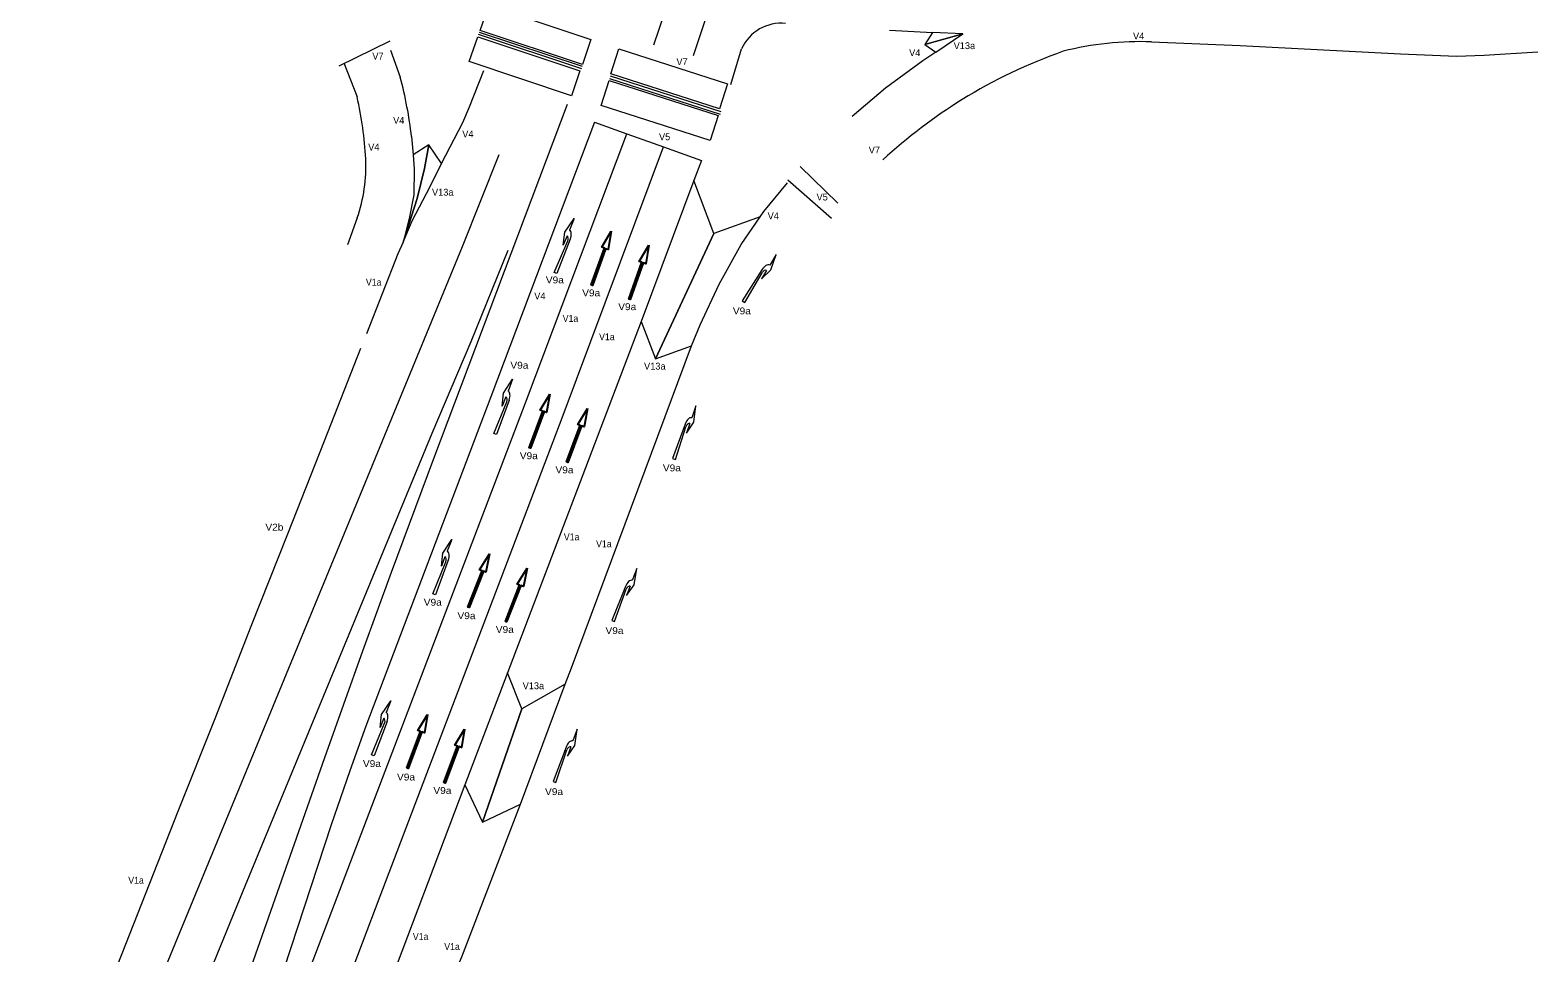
# Model space of a CAD drawing. Extents: x -598770 to -598612, y -1162818 to -1162391.
# Drawn here: x -598743 to -598611.6, y -1162737.1 to -1162656.8 of the extents above; entities that cross this region are included whole.
import ezdxf

# ---------------------------------------------------------------- set-up
doc = ezdxf.new("R2010")
doc.units = 0
doc.header["$LTSCALE"] = 0.24
doc.layers.add('1', color=7, linetype='Continuous', lineweight=25)
doc.layers.add('47', color=7, linetype='Continuous', lineweight=13)

msp = doc.modelspace()

# ---------------------------------------------------------------- linework, layer by layer
at = {"layer": '1'}
for points in [[(-598692.356, -1162674.292), (-598692.613, -1162675.9), (-598692.839, -1162675.819), (-598693.984, -1162679.02), (-598694.096, -1162678.98), (-598692.952, -1162675.778), (-598693.178, -1162675.698)], [(-598689.086, -1162675.522), (-598689.343, -1162677.13), (-598689.569, -1162677.049), (-598690.714, -1162680.25), (-598690.826, -1162680.21), (-598689.682, -1162677.008), (-598689.908, -1162676.928)], [(-598697.702, -1162688.485), (-598697.98, -1162690.089), (-598698.205, -1162690.005), (-598699.394, -1162693.191), (-598699.506, -1162693.149), (-598698.318, -1162689.964), (-598698.543, -1162689.88)], [(-598694.432, -1162689.725), (-598694.71, -1162691.329), (-598694.935, -1162691.245), (-598696.124, -1162694.431), (-598696.236, -1162694.389), (-598695.048, -1162691.204), (-598695.273, -1162691.12)], [(-598702.961, -1162702.397), (-598703.267, -1162703.996), (-598703.49, -1162703.908), (-598704.734, -1162707.072), (-598704.846, -1162707.028), (-598703.602, -1162703.864), (-598703.825, -1162703.776)], [(-598699.691, -1162703.647), (-598699.997, -1162705.246), (-598700.22, -1162705.158), (-598701.464, -1162708.322), (-598701.576, -1162708.278), (-598700.332, -1162705.114), (-598700.555, -1162705.026)], [(-598708.358, -1162716.373), (-598708.634, -1162717.978), (-598708.859, -1162717.894), (-598710.044, -1162721.081), (-598710.156, -1162721.039), (-598708.971, -1162717.852), (-598709.196, -1162717.769)], [(-598705.127, -1162717.661), (-598705.41, -1162719.264), (-598705.635, -1162719.18), (-598706.834, -1162722.361), (-598706.946, -1162722.319), (-598705.747, -1162719.137), (-598705.972, -1162719.053)]]:
    msp.add_lwpolyline(points, close=True, dxfattribs=at)
at = {"layer": '47'}
for p, q in [((-598668.09, -1162656.8), (-598664.36, -1162657)), ((-598716.061, -1162659.896), (-598711.608, -1162657.714)), ((-598694.919, -1162660.156), (-598703.928, -1162657.18)), ((-598694.841, -1162659.944), (-598703.821, -1162656.98)), ((-598711.6, -1162658.54), (-598710.74, -1162660.89)), ((-598681.94, -1162661.53), (-598680.99, -1162658.42)), ((-598715.66, -1162659.63), (-598714.5, -1162662.6)), ((-598692.437, -1162660.774), (-598682.807, -1162663.859)), ((-598692.511, -1162661), (-598682.858, -1162664.093)), ((-598709.75, -1162666.06), (-598709.62, -1162667.66)), ((-598699.81, -1162689.25), (-598691, -1162665.83)), ((-598696.64, -1162690.56), (-598687.79, -1162666.96)), ((-598684.48, -1162668.14), (-598685.14, -1162669.89)), ((-598675.873, -1162668.667), (-598672.616, -1162671.867)), ((-598676.96, -1162669.82), (-598673.16, -1162673.16)), ((-598714.48, -1162673.14), (-598715.32, -1162675.47)), ((-598695.58, -1162673.19), (-598695.997, -1162674.208)), ((-598677.974, -1162676.318), (-598678.544, -1162677.259)), ((-598700.952, -1162687.193), (-598701.345, -1162688.221)), ((-598684.98, -1162689.505), (-598685.335, -1162690.546)), ((-598706.246, -1162701.138), (-598706.643, -1162702.164)), ((-598690.124, -1162703.683), (-598690.514, -1162704.711)), ((-598711.571, -1162715.183), (-598711.978, -1162716.205)), ((-598695.327, -1162717.656), (-598695.699, -1162718.691))]:
    msp.add_line(p, q, dxfattribs=at)
for points in [[(-598685.18, -1162659.01), (-598682.44, -1162650.81), (-598678.78, -1162639.81), (-598676.01, -1162631.49), (-598669.81, -1162609.43), (-598665.71, -1162592.63), (-598660.52, -1162567.28), (-598657.82, -1162550.24), (-598655.55, -1162533.08), (-598653.64, -1162512.9), (-598653.24, -1162507.21), (-598652.17, -1162486.96), (-598650.81, -1162443.8), (-598650.17, -1162405.3)], [(-598688.64, -1162658.06), (-598686.79, -1162652.59), (-598679.89, -1162631.9)], [(-598645.26, -1162657.81), (-598637.54, -1162658.14), (-598623.58, -1162658.85), (-598618.7, -1162659.04), (-598616.28, -1162658.97), (-598611.6, -1162658.68)], [(-598664.07, -1162658.72), (-598665.2, -1162659.47), (-598668.46, -1162661.85), (-598671.36, -1162664.3)], [(-598707.13, -1162668.41), (-598705.27, -1162664.84), (-598704.69, -1162663.46), (-598703.44, -1162660.31)], [(-598696.2, -1162663.26), (-598707.83, -1162694.12), (-598711.54, -1162704.01), (-598714.04, -1162710.86), (-598717.34, -1162720.17), (-598728.64, -1162752.3), (-598735.08, -1162769.26)], [(-598693.82, -1162664.79), (-598702.84, -1162688.72), (-598713.75, -1162717.39), (-598715.12, -1162721.28), (-598716.75, -1162725.99), (-598732.65, -1162774.4)], [(-598693.82, -1162664.79), (-598691, -1162665.83), (-598687.79, -1162666.96), (-598684.48, -1162668.14)], [(-598702.14, -1162667.64), (-598705.35, -1162675.66), (-598715.83, -1162701.11), (-598732.7, -1162742.03), (-598734.74, -1162747.28), (-598741.96, -1162766.21), (-598742.99, -1162769.03)], [(-598679.38, -1162673.06), (-598679.05, -1162672.57), (-598677, -1162670.08)], [(-598696.202, -1162674.708), (-598696.529, -1162675.503), (-598696.389, -1162674.372), (-598695.58, -1162673.19)], [(-598710.49, -1162675.25), (-598710.94, -1162676.27), (-598713.68, -1162683.24)], [(-598695.919, -1162674.997), (-598697.084, -1162677.977), (-598697.316, -1162677.883), (-598696.131, -1162675.126)], [(-598701.36, -1162675.97), (-598704.6, -1162683.92), (-598707.98, -1162691.91), (-598724.47, -1162731.76), (-598730.99, -1162747.75)], [(-598678.823, -1162677.721), (-598679.269, -1162678.457), (-598678.442, -1162677.671), (-598677.974, -1162676.318)], [(-598679.224, -1162677.665), (-598680.927, -1162680.375), (-598680.713, -1162680.505), (-598679.202, -1162677.912)], [(-598689.73, -1162682.17), (-598701.39, -1162712.77), (-598705.1, -1162722.51)], [(-598714.19, -1162684.51), (-598717.37, -1162692.57), (-598720.57, -1162700.67), (-598723.76, -1162708.71), (-598726.91, -1162716.76), (-598730.11, -1162724.83), (-598736.46, -1162740.9)], [(-598696.36, -1162713.74), (-598695.82, -1162712.33), (-598685.36, -1162684.28)], [(-598701.538, -1162688.725), (-598701.846, -1162689.528), (-598701.733, -1162688.394), (-598700.952, -1162687.193)], [(-598726.06, -1162758.02), (-598723.44, -1162751.19), (-598699.81, -1162689.25)], [(-598701.248, -1162689.007), (-598702.343, -1162692.015), (-598702.577, -1162691.925), (-598701.457, -1162689.142)], [(-598685.51, -1162691.057), (-598685.788, -1162691.871), (-598685.149, -1162690.927), (-598684.98, -1162689.505)], [(-598722.67, -1162759.28), (-598718.64, -1162748.46), (-598712.49, -1162732.21), (-598696.64, -1162690.56)], [(-598685.914, -1162691.089), (-598686.998, -1162694.1), (-598686.762, -1162694.18), (-598685.839, -1162691.325)], [(-598706.838, -1162702.668), (-598707.148, -1162703.47), (-598707.031, -1162702.336), (-598706.246, -1162701.138)], [(-598706.549, -1162702.951), (-598707.653, -1162705.955), (-598707.887, -1162705.865), (-598706.758, -1162703.085)], [(-598690.706, -1162705.216), (-598691.012, -1162706.02), (-598690.34, -1162705.098), (-598690.124, -1162703.683)], [(-598691.111, -1162705.233), (-598692.297, -1162708.206), (-598692.063, -1162708.294), (-598691.044, -1162705.472)], [(-598712.177, -1162716.707), (-598712.495, -1162717.506), (-598712.367, -1162716.373), (-598711.571, -1162715.183)], [(-598711.891, -1162716.993), (-598713.024, -1162719.986), (-598713.256, -1162719.894), (-598712.101, -1162717.125)], [(-598695.882, -1162719.199), (-598696.172, -1162720.009), (-598695.518, -1162719.075), (-598695.327, -1162717.656)], [(-598696.286, -1162719.224), (-598697.418, -1162722.218), (-598697.182, -1162722.302), (-598696.215, -1162719.462)], [(-598705.1, -1162722.51), (-598712.39, -1162741.77), (-598713.95, -1162745.97), (-598721.88, -1162767.78)], [(-598720.58, -1162768.16), (-598715.47, -1162758.87), (-598711.57, -1162751.14), (-598707.93, -1162743.46), (-598705.37, -1162737.49), (-598700.25, -1162724.18)]]:
    msp.add_lwpolyline(points, dxfattribs=at)
for points in [[(-598703.027, -1162654.647), (-598694.128, -1162657.617), (-598694.848, -1162659.777), (-598703.766, -1162656.807)], [(-598703.982, -1162657.365), (-598695.083, -1162660.335), (-598695.803, -1162662.495), (-598704.721, -1162659.525)], [(-598664.36, -1162657), (-598665.03, -1162658.05), (-598661.72, -1162657.12)], [(-598665.03, -1162658.05), (-598664.07, -1162658.72), (-598661.72, -1162657.12)], [(-598691.7, -1162658.424), (-598682.207, -1162661.466), (-598682.903, -1162663.64), (-598692.397, -1162660.598)], [(-598692.534, -1162661.185), (-598683.041, -1162664.227), (-598683.737, -1162666.401), (-598693.231, -1162663.359)], [(-598708.25, -1162666.77), (-598708.62, -1162668.85), (-598709.26, -1162671.44), (-598710.49, -1162675.25), (-598709.69, -1162673.39), (-598708.13, -1162670.41), (-598707.13, -1162668.41)], [(-598708.25, -1162666.77), (-598709.62, -1162667.66), (-598709.52, -1162668.89), (-598709.56, -1162671.14), (-598709.95, -1162673.19), (-598710.49, -1162675.25), (-598709.26, -1162671.44), (-598708.62, -1162668.85)], [(-598685.14, -1162669.89), (-598689.73, -1162682.17), (-598688.48, -1162685.4), (-598683.41, -1162674.51)], [(-598683.41, -1162674.51), (-598688.48, -1162685.4), (-598685.36, -1162684.28), (-598684.61, -1162682.46), (-598682.95, -1162678.92), (-598681.02, -1162675.46), (-598679.38, -1162673.06)], [(-598701.39, -1162712.77), (-598705.1, -1162722.51), (-598703.56, -1162725.76), (-598700.14, -1162715.88)], [(-598696.36, -1162713.74), (-598700.14, -1162715.88), (-598703.56, -1162725.76), (-598700.25, -1162724.18)]]:
    msp.add_lwpolyline(points, close=True, dxfattribs=at)
for centre, radius, start, end in [((-598677.536, -1162659.9634), 3.7832, 84.1441, 155.92246), ((-598646.2614, -1162685.0507), 27.2591, 87.89467, 104.24712), ((-598637.7345, -1162701.8354), 45.813, 109.42414, 121.65897), ((-598745.2256, -1162670.1734), 35.7132, 6.61393, 15.06668), ((-598744.1809, -1162669.4744), 30.4666, 2.77392, 13.04041), ((-598636.2065, -1162703.678), 48.1845, 122.05557, 132.37198), ((-598727.5693, -1162668.6592), 13.835, 341.10251, 2.73093)]:
    msp.add_arc(centre, radius, start, end, dxfattribs=at)
for centre, major_axis, ratio, start_param, end_param in [((-598696.3391, -1162675.0408), (0.1366, 0.3331), 0.625, 4.71238898, 6.28318531), ((-598696.2631, -1162674.8558), (0.2657, 0.6476), 0.531429, 4.71238898, 6.28318531), ((-598678.906, -1162677.8578), (-0.3625, -0.5988), 0.531429, 3.14159265, 4.71238898), ((-598679.0096, -1162678.0289), (-0.1864, -0.308), 0.625, 3.14159265, 4.71238898), ((-598701.5959, -1162688.8745), (0.2504, 0.6537), 0.531429, 4.71238898, 6.28318531), ((-598701.6674, -1162689.0613), (0.1288, 0.3362), 0.625, 4.71238898, 6.28318531), ((-598685.5616, -1162691.2087), (-0.2263, -0.6624), 0.531429, 3.14159265, 4.71238898), ((-598685.6262, -1162691.3979), (-0.1164, -0.3407), 0.625, 3.14159265, 4.71238898), ((-598706.9681, -1162703.0039), (0.1298, 0.3358), 0.625, 4.71238898, 6.28318531), ((-598706.8959, -1162702.8173), (0.2525, 0.6529), 0.531429, 4.71238898, 6.28318531), ((-598690.7628, -1162705.3651), (-0.2486, -0.6544), 0.531429, 3.14159265, 4.71238898), ((-598690.8338, -1162705.5521), (-0.1279, -0.3365), 0.625, 3.14159265, 4.71238898), ((-598712.3104, -1162717.0417), (0.133, 0.3345), 0.625, 4.71238898, 6.28318531), ((-598712.2365, -1162716.8558), (0.2587, 0.6504), 0.531429, 4.71238898, 6.28318531), ((-598695.9357, -1162719.3497), (-0.2366, -0.6588), 0.531429, 3.14159265, 4.71238898), ((-598696.0033, -1162719.5379), (-0.1217, -0.3388), 0.625, 3.14159265, 4.71238898)]:
    msp.add_ellipse(centre, major_axis=major_axis, ratio=ratio, start_param=start_param, end_param=end_param, dxfattribs=at)

# ---------------------------------------------------------------- texts
for s, p in [('V13a', (-598662.51, -1162658.44)), ('V4', (-598646.88, -1162657.6)), ('V7', (-598713.17, -1162659.35)), ('V7', (-598686.67, -1162659.83)), ('V4', (-598666.39, -1162659.05)), ('V4', (-598711.36, -1162664.94)), ('V4', (-598705.33, -1162666.13)), ('V5', (-598688.19, -1162666.37)), ('V4', (-598713.53, -1162667.27)), ('V7', (-598669.91, -1162667.53)), ('V13a', (-598707.97, -1162671.2)), ('V5', (-598674.46, -1162671.62)), ('V4', (-598678.72, -1162673.26)), ('V4', (-598699.06, -1162680.24)), ('V13a', (-598689.49, -1162686.35)), ('V13a', (-598700.07, -1162714.18))]:
    msp.add_text(s, height=0.6, dxfattribs=at).set_placement(p)
for s, width, p in [('V1a', 0.95, (-598713.73, -1162679.04)), ('V9a', 1.1, (-598698.05, -1162678.84)), ('V9a', 1.1, (-598694.88, -1162679.97)), ('V9a', 1.1, (-598691.74, -1162681.17)), ('V1a', 0.95, (-598696.58, -1162682.19)), ('V9a', 1.1, (-598681.75, -1162681.54)), ('V1a', 0.95, (-598693.41, -1162683.79)), ('V9a', 1.1, (-598701.14, -1162686.27)), ('V9a', 1.1, (-598700.32, -1162694.15)), ('V9a', 1.1, (-598697.21, -1162695.38)), ('V9a', 1.1, (-598687.85, -1162695.21)), ('V2b', 1.1, (-598722.49, -1162700.37)), ('V1a', 0.95, (-598696.48, -1162701.22)), ('V1a', 0.95, (-598693.67, -1162701.82)), ('V9a', 1.1, (-598708.69, -1162706.91)), ('V9a', 1.1, (-598705.75, -1162708.08)), ('V9a', 1.1, (-598702.41, -1162709.28)), ('V9a', 1.1, (-598692.85, -1162709.38)), ('V9a', 1.1, (-598713.99, -1162720.96)), ('V9a', 1.1, (-598711.02, -1162722.13)), ('V9a', 1.1, (-598707.85, -1162723.3)), ('V9a', 1.1, (-598698.12, -1162723.4)), ('V1a', 0.95, (-598734.44, -1162731.12)), ('V1a', 0.95, (-598709.64, -1162736.02)), ('V1a', 0.95, (-598706.9, -1162736.89))]:
    msp.add_text(s, height=0.6, dxfattribs=dict(at, width=width)).set_placement(p)

doc.saveas('drawing.dxf')
